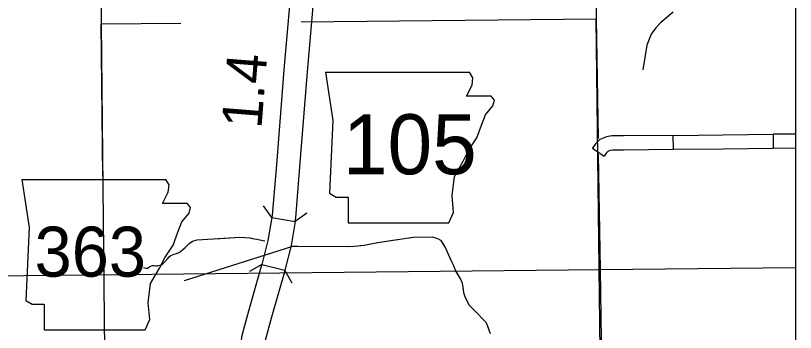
# Model space of a CAD drawing. Extents: x 1374139 to 1377472, y 1168351 to 1170484.
# Drawn here: x 1376432.5 to 1376597.4, y 1169182.8 to 1169249.6 of the extents above; entities that cross this region are included whole.
import ezdxf

# ---------------------------------------------------------------- set-up
doc = ezdxf.new("R2010")
doc.units = 0
doc.layers.add('26', color=7, linetype='Continuous')
doc.layers.add('Default', color=7, linetype='Continuous')

msp = doc.modelspace()

# ---------------------------------------------------------------- linework, layer by layer
at = {"layer": '26'}
msp.add_lwpolyline([(1375090, 1169579.43), (1376597.43, 1169579.43), (1376597.43, 1168653.79), (1375090, 1168653.79)], close=True, dxfattribs=at)
at = {"layer": 'Default'}
for p, q in [((1376558.91, 1168931.59), (1376555.31, 1169248.93)), ((1376450.62, 1169247.9), (1376454.96, 1168833.71)), ((1376498.08, 1169237.68), (1376499.6, 1169227.53)), ((1376529.21, 1169236.5), (1376528.51, 1169237.67)), ((1376529.04, 1169234.97), (1376529.21, 1169236.5)), ((1376527.86, 1169232.61), (1376529.04, 1169234.97)), ((1376533.1, 1169232.61), (1376527.86, 1169232.61)), ((1376533.78, 1169231.76), (1376533.1, 1169232.61)), ((1376531.92, 1169228.72), (1376533.44, 1169230.58)), ((1376533.44, 1169230.58), (1376533.78, 1169231.76)), ((1376531.07, 1169226.52), (1376531.92, 1169228.72)), ((1376499.6, 1169227.53), (1376498.93, 1169212.14)), ((1376530.06, 1169223.81), (1376531.07, 1169226.52)), ((1376528.36, 1169221.27), (1376530.06, 1169223.81)), ((1376571.63, 1169221.36), (1376571.6, 1169224.36)), ((1376592.72, 1169224.58), (1376592.75, 1169221.58)), ((1376527.18, 1169218.9), (1376528.36, 1169221.27)), ((1376525.32, 1169215.69), (1376527.18, 1169218.9)), ((1376524.81, 1169211.63), (1376525.32, 1169215.69)), ((1376433.84, 1169215.07), (1376435.36, 1169204.92)), ((1376464.97, 1169213.88), (1376464.27, 1169215.05)), ((1376464.8, 1169212.36), (1376464.97, 1169213.88)), ((1376463.62, 1169209.99), (1376464.8, 1169212.36)), ((1376498.93, 1169212.14), (1376500.28, 1169211.29)), ((1376500.28, 1169211.29), (1376502.82, 1169211.29)), ((1376502.82, 1169211.29), (1376502.82, 1169205.88)), ((1376525.15, 1169208.08), (1376524.81, 1169211.63)), ((1376468.86, 1169209.99), (1376463.62, 1169209.99)), ((1376469.54, 1169209.15), (1376468.86, 1169209.99)), ((1376469.2, 1169207.96), (1376469.54, 1169209.15)), ((1376467.68, 1169206.1), (1376469.2, 1169207.96)), ((1376524.13, 1169205.88), (1376525.15, 1169208.08)), ((1376466.83, 1169203.9), (1376467.68, 1169206.1)), ((1376486.7, 1169207.01), (1376491.63, 1169206.18)), ((1376502.82, 1169205.88), (1376524.13, 1169205.88)), ((1376435.36, 1169204.92), (1376434.69, 1169189.52)), ((1376465.82, 1169201.2), (1376466.83, 1169203.9)), ((1376464.12, 1169198.66), (1376465.82, 1169201.2)), ((1376462.94, 1169196.29), (1376464.12, 1169198.66)), ((1376434.26, 1169194.78), (1376556.11, 1169196.03)), ((1376461.08, 1169193.07), (1376462.94, 1169196.29)), ((1376484.62, 1169197.1), (1376489.47, 1169195.88)), ((1376460.57, 1169189.01), (1376461.08, 1169193.07)), ((1376434.69, 1169189.52), (1376436.04, 1169188.68)), ((1376436.04, 1169188.68), (1376438.58, 1169188.68)), ((1376438.58, 1169188.68), (1376438.58, 1169183.26)), ((1376460.91, 1169185.46), (1376460.57, 1169189.01)), ((1376459.89, 1169183.26), (1376460.91, 1169185.46)), ((1376438.58, 1169183.26), (1376459.89, 1169183.26))]:
    msp.add_line(p, q, dxfattribs=at)
for points in [[(1376554.51, 1169301.83), (1376555.31, 1169248.93)], [(1376450.04, 1169300.28), (1376450.62, 1169247.9)], [(1376490.74, 1169259.21), (1376490.91, 1169257.42), (1376489.27, 1169238.16), (1376487.67, 1169218.15), (1376486.79, 1169207.54), (1376486.7, 1169207.01)], [(1376491.63, 1169206.18), (1376491.76, 1169206.92), (1376492.65, 1169217.74), (1376494.25, 1169237.75), (1376495.93, 1169257.44), (1376495.71, 1169259.68)], [(1376571.59, 1169250.36), (1376568.96, 1169248.22), (1376567.88, 1169247.08), (1376566.92, 1169245.72), (1376565.99, 1169243.4), (1376565.19, 1169238.17)], [(1376492.89, 1169248.31), (1376555.31, 1169248.93), (1376555.69, 1169223.71)], [(1376450.97, 1169215.74), (1376450.62, 1169247.9), (1376467.47, 1169248.06)], [(1376498.08, 1169237.68), (1376528.51, 1169237.67)], [(1376561.04, 1169224.25), (1376558.61, 1169224.23), (1376557.45, 1169224.06), (1376556.1, 1169223.49), (1376555.13, 1169222.59), (1376554.5, 1169221.66), (1376556.97, 1169219.97)], [(1376571.6, 1169224.36), (1376561.04, 1169224.25)], [(1376571.6, 1169224.36), (1376582.16, 1169224.47)], [(1376582.16, 1169224.47), (1376592.72, 1169224.58)], [(1376597.43, 1169224.63), (1376592.72, 1169224.58)], [(1376555.74, 1169220.39), (1376556.11, 1169196.03), (1376556.9, 1169141.38)], [(1376561.07, 1169221.25), (1376558.84, 1169221.23), (1376558.27, 1169221.15), (1376557.76, 1169220.93), (1376557.42, 1169220.62), (1376556.97, 1169219.97)], [(1376571.63, 1169221.36), (1376561.07, 1169221.25)], [(1376582.19, 1169221.47), (1376571.63, 1169221.36)], [(1376592.75, 1169221.58), (1376582.19, 1169221.47)], [(1376597.43, 1169221.63), (1376592.75, 1169221.58)], [(1376433.84, 1169215.07), (1376464.27, 1169215.05)], [(1376486.7, 1169207.01), (1376484.96, 1169209.46)], [(1376494.08, 1169207.92), (1376491.63, 1169206.18)], [(1376486.7, 1169207.01), (1376485.88, 1169202.12), (1376484.62, 1169197.1)], [(1376491.63, 1169206.18), (1376490.78, 1169201.1), (1376489.47, 1169195.88)], [(1376459.58, 1169196.43), (1376460.11, 1169196.28), (1376460.43, 1169196.31), (1376460.62, 1169196.42), (1376460.84, 1169196.6), (1376461.27, 1169196.81), (1376461.45, 1169196.9), (1376461.79, 1169196.87), (1376462.15, 1169196.84), (1376462.45, 1169196.8), (1376462.69, 1169196.87), (1376463.27, 1169197.02), (1376463.66, 1169197.23), (1376464.01, 1169197.59), (1376464.7, 1169198.34), (1376464.97, 1169198.71), (1376465.32, 1169199), (1376466.03, 1169199.24), (1376466.55, 1169199.4), (1376467.1, 1169199.65), (1376467.79, 1169200.15), (1376468.4, 1169200.67), (1376469.22, 1169201.55), (1376469.93, 1169202.03), (1376470.92, 1169202.3), (1376479.96, 1169202.85), (1376482.06, 1169202.7), (1376483.03, 1169202.52), (1376483.53, 1169202.41), (1376484.19, 1169202.27), (1376485.23, 1169202.09)], [(1376465.18, 1169198.89), (1376465.32, 1169199), (1376466.03, 1169199.24), (1376466.55, 1169199.4), (1376467.1, 1169199.65), (1376467.79, 1169200.15), (1376468.4, 1169200.67), (1376469.22, 1169201.55), (1376469.93, 1169202.03), (1376470.92, 1169202.3), (1376472.02, 1169202.36)], [(1376468.27, 1169193.7), (1376491.12, 1169200.97), (1376491.42, 1169200.97), (1376503.2, 1169200.91), (1376504.89, 1169201.01), (1376506.23, 1169201.17), (1376507.96, 1169201.51), (1376509.1, 1169201.72), (1376516.61, 1169202.85), (1376520.62, 1169202.92), (1376521.53, 1169202.68), (1376521.85, 1169202.53), (1376522.38, 1169202.2), (1376522.69, 1169201.8), (1376522.92, 1169201.39), (1376523.4, 1169200.56), (1376523.8, 1169199.77), (1376524.69, 1169197.72), (1376525.09, 1169196.85), (1376525.55, 1169195.76), (1376526.78, 1169193.68), (1376526.93, 1169193.14), (1376527.1, 1169192.24), (1376527.26, 1169191.18), (1376527.52, 1169190.33), (1376527.92, 1169189.38), (1376528.42, 1169188.53), (1376530.39, 1169186.51), (1376531.11, 1169185.72), (1376531.87, 1169184.98), (1376532.14, 1169184.49), (1376532.89, 1169182.5)], [(1376474.65, 1169202.52), (1376479.96, 1169202.85), (1376482.06, 1169202.7), (1376482.55, 1169202.61)], [(1376505.41, 1169201.07), (1376506.23, 1169201.17), (1376507.96, 1169201.51), (1376509.1, 1169201.72), (1376513.23, 1169202.34)], [(1376515.84, 1169202.74), (1376516.61, 1169202.85), (1376520.62, 1169202.92), (1376521.53, 1169202.68), (1376521.85, 1169202.53), (1376522.38, 1169202.2), (1376522.69, 1169201.8), (1376522.92, 1169201.39), (1376523.03, 1169201.19)], [(1376485.14, 1169202.1), (1376485.23, 1169202.09)], [(1376490.76, 1169200.98), (1376491.42, 1169200.97), (1376492.22, 1169200.97)], [(1376494.86, 1169200.95), (1376502.78, 1169200.91)], [(1376524.21, 1169198.82), (1376524.69, 1169197.72), (1376525.09, 1169196.85), (1376525.55, 1169195.76), (1376525.86, 1169195.23)], [(1376480.13, 1169142.51), (1376480.32, 1169150.65), (1376479.97, 1169167.59), (1376480.09, 1169170.99), (1376480.24, 1169179.71), (1376480.34, 1169181.85), (1376481.84, 1169187.3), (1376484.61, 1169197.04), (1376484.62, 1169197.1)], [(1376482.03, 1169195.7), (1376484.64, 1169197.17)], [(1376489.47, 1169195.88), (1376489.44, 1169195.75), (1376486.65, 1169185.96), (1376485.31, 1169181.05), (1376485.24, 1169179.54), (1376485.09, 1169170.85), (1376484.97, 1169167.55), (1376485.33, 1169150.64), (1376485.16, 1169143.91)], [(1376489.46, 1169195.81), (1376490.92, 1169193.2)], [(1376556.11, 1169196.03), (1376597.43, 1169196.47)], [(1376407.55, 1169194.62), (1376434.26, 1169194.78)], [(1376525.86, 1169195.23), (1376526.78, 1169193.68), (1376526.93, 1169193.14), (1376527.1, 1169192.24), (1376527.2, 1169191.57)], [(1376528.09, 1169189.1), (1376528.42, 1169188.53), (1376530.39, 1169186.51), (1376531.11, 1169185.72), (1376531.87, 1169184.98), (1376532.14, 1169184.49), (1376532.76, 1169182.85)]]:
    msp.add_lwpolyline(points, dxfattribs=at)

# ---------------------------------------------------------------- texts
msp.add_text('1.4', height=8.448, rotation=85.4351, dxfattribs=at).set_placement((1376484.49, 1169225.64))
for s, height, p in [('105', 12.672, (1376501.76, 1169216.14)), ('363', 10.56, (1376436.54, 1169194.52))]:
    msp.add_text(s, height=height, dxfattribs=at).set_placement(p)

doc.saveas('drawing.dxf')
